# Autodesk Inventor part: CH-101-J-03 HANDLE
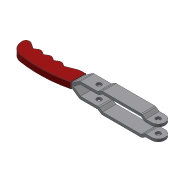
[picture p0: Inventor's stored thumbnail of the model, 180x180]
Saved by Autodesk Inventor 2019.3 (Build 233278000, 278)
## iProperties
Created: 2012-09
Part Number: CH-101-J-03 HANDLE
Material: Ogólny
Document SubType Name: Modeling
Designer: CADENGINEERING4
Density: 1 g/cm^3
Appearance: Domyślna
Author: CADENGINEERING4
Revision Number: ÈÎºÎ
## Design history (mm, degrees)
feature "Ô²½Ç3"
node "Bryła1"
